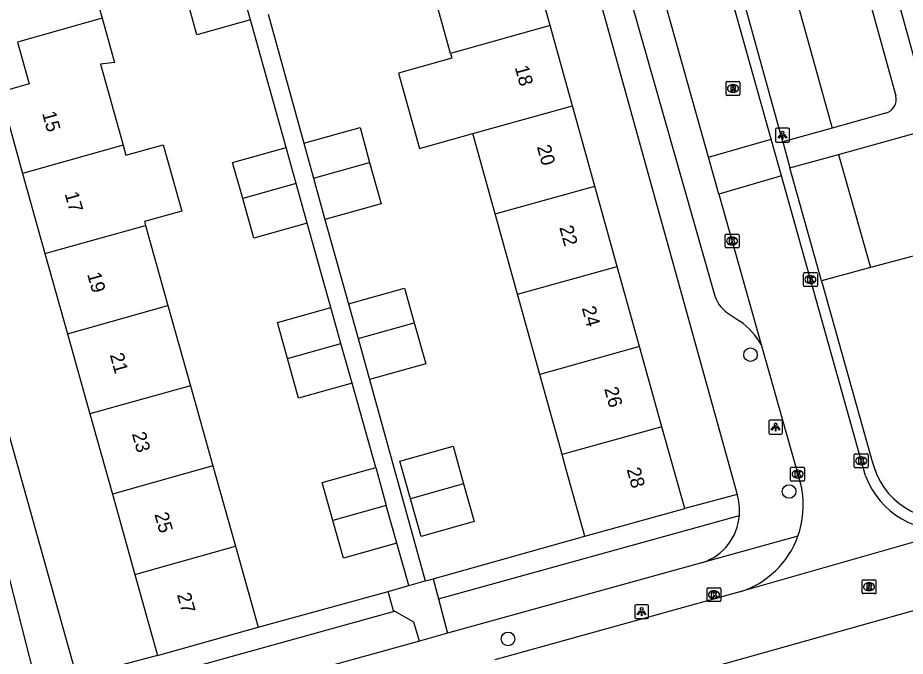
# Model space of a CAD drawing. Extents: x 159053 to 160041, y 380450 to 381422.
# Drawn here: x 159237.4 to 159301.4, y 380938.4 to 380984.4 of the extents above; entities that cross this region are included whole.
import ezdxf

# ---------------------------------------------------------------- set-up
doc = ezdxf.new("R2010")
doc.units = 0
for name, color, linetype in [('IMGEO_Boom', 7, 'Continuous'), ('IMGEO_Groenvoorziening', 7, 'Continuous'), ('IMGEO_Kolk', 7, 'Continuous'), ('IMGEO_Lichtpunt', 7, 'Continuous'), ('IMGEO_Pand', 7, 'Continuous'), ('IMGEO_Pand_nummerreeks', 7, 'Continuous'), ('IMGEO_Rijbaan_lokaal_open', 7, 'Continuous'), ('IMGEO_Rioolput', 7, 'Continuous'), ('IMGEO_Voetpad_halfverhard', 7, 'Continuous'), ('IMGEO_Voetpad_open', 7, 'Continuous')]:
    doc.layers.add(name, color=color, linetype=linetype)

msp = doc.modelspace()

# ---------------------------------------------------------------- linework, layer by layer
at = {"layer": 'IMGEO_Boom'}
for centre in [(159290.213, 380960.156), (159292.995, 380950.304), (159272.756, 380939.682)]:
    msp.add_circle(centre, 0.489, dxfattribs=at)
at = {"layer": 'IMGEO_Groenvoorziening'}
for points in [[(159291.218, 381004.807), (159292.969, 380998.465), (159290.211, 380997.678), (159296.09, 380976.486)], [(159296.56, 380974.584), (159298.858, 380966.431)], [(159308.436, 380968.993), (159298.858, 380966.431)], [(159298.858, 380966.431), (159295.334, 380965.488)], [(159289.244, 380950.092), (159285.477, 380949.072)], [(159267.741, 380942.562), (159289.412, 380948.582)], [(159267.352, 380944.011), (159278.291, 380947.073)], [(159254.754, 380940.525), (159264.121, 380943.101)], [(159242.353, 380935.51), (159264.567, 380941.681)], [(159247.51, 380938.496), (159241.698, 380936.943)]]:
    msp.add_lwpolyline(points, dxfattribs=at)
at = {"layer": 'IMGEO_Kolk'}
for p, q in [((159288.387, 380967.922), (159288.387, 380968.774)), ((159288.462, 380968.848), (159289.314, 380968.848)), ((159288.875, 380968.628), (159288.9, 380968.628)), ((159289.388, 380968.774), (159289.388, 380967.922)), ((159289.314, 380967.848), (159288.462, 380967.848)), ((159288.898, 380968.068), (159288.873, 380968.068)), ((159294.028, 380965.142), (159294.028, 380965.994)), ((159294.103, 380966.068), (159294.955, 380966.068)), ((159295.029, 380965.994), (159295.029, 380965.142)), ((159294.539, 380965.288), (159294.514, 380965.288)), ((159294.516, 380965.848), (159294.541, 380965.848)), ((159294.955, 380965.068), (159294.103, 380965.068)), ((159297.686, 380952.087), (159297.686, 380952.939)), ((159297.761, 380953.013), (159298.613, 380953.013)), ((159298.174, 380952.793), (159298.199, 380952.793)), ((159298.687, 380952.939), (159298.687, 380952.087)), ((159293.107, 380951.124), (159293.107, 380951.976)), ((159293.182, 380952.05), (159294.034, 380952.05)), ((159294.108, 380951.976), (159294.108, 380951.124)), ((159298.613, 380952.013), (159297.761, 380952.013)), ((159298.197, 380952.233), (159298.172, 380952.233)), ((159293.618, 380951.27), (159293.593, 380951.27)), ((159293.595, 380951.83), (159293.62, 380951.83)), ((159294.034, 380951.05), (159293.182, 380951.05)), ((159287.084, 380942.442), (159287.084, 380943.294)), ((159287.159, 380943.368), (159288.011, 380943.368)), ((159287.572, 380943.148), (159287.597, 380943.148)), ((159288.085, 380943.294), (159288.085, 380942.442)), ((159288.011, 380942.368), (159287.159, 380942.368)), ((159287.595, 380942.588), (159287.57, 380942.588))]:
    msp.add_line(p, q, dxfattribs=at)
for points in [[(159288.387, 380967.922), (159288.387, 380968.774)], [(159288.462, 380968.848), (159289.314, 380968.848)], [(159288.708, 380968.548), (159288.831, 380968.548), (159288.831, 380968.397), (159288.961, 380968.548), (159289.125, 380968.548), (159288.979, 380968.397), (159289.132, 380968.148), (159288.98, 380968.148), (159288.895, 380968.312), (159288.831, 380968.245), (159288.831, 380968.148), (159288.708, 380968.148), (159288.708, 380968.548)], [(159289.388, 380968.774), (159289.388, 380967.922)], [(159289.314, 380967.848), (159288.462, 380967.848)], [(159294.028, 380965.142), (159294.028, 380965.994)], [(159294.103, 380966.068), (159294.955, 380966.068)], [(159295.029, 380965.994), (159295.029, 380965.142)], [(159294.349, 380965.768), (159294.472, 380965.768), (159294.472, 380965.617), (159294.602, 380965.768), (159294.766, 380965.768), (159294.62, 380965.617), (159294.773, 380965.368), (159294.621, 380965.368), (159294.536, 380965.532), (159294.472, 380965.465), (159294.472, 380965.368), (159294.349, 380965.368), (159294.349, 380965.768)], [(159294.955, 380965.068), (159294.103, 380965.068)], [(159297.686, 380952.087), (159297.686, 380952.939)], [(159297.761, 380953.013), (159298.613, 380953.013)], [(159298.007, 380952.713), (159298.13, 380952.713), (159298.13, 380952.562), (159298.26, 380952.713), (159298.424, 380952.713), (159298.278, 380952.562), (159298.431, 380952.313), (159298.279, 380952.313), (159298.194, 380952.477), (159298.13, 380952.41), (159298.13, 380952.313), (159298.007, 380952.313), (159298.007, 380952.713)], [(159298.687, 380952.939), (159298.687, 380952.087)], [(159293.107, 380951.124), (159293.107, 380951.976)], [(159293.182, 380952.05), (159294.034, 380952.05)], [(159294.108, 380951.976), (159294.108, 380951.124)], [(159298.613, 380952.013), (159297.761, 380952.013)], [(159293.428, 380951.75), (159293.551, 380951.75), (159293.551, 380951.599), (159293.681, 380951.75), (159293.845, 380951.75), (159293.699, 380951.599), (159293.852, 380951.35), (159293.7, 380951.35), (159293.615, 380951.514), (159293.551, 380951.447), (159293.551, 380951.35), (159293.428, 380951.35), (159293.428, 380951.75)], [(159294.034, 380951.05), (159293.182, 380951.05)], [(159287.084, 380942.442), (159287.084, 380943.294)], [(159287.159, 380943.368), (159288.011, 380943.368)], [(159287.405, 380943.068), (159287.528, 380943.068), (159287.528, 380942.917), (159287.658, 380943.068), (159287.822, 380943.068), (159287.676, 380942.917), (159287.829, 380942.668), (159287.677, 380942.668), (159287.592, 380942.832), (159287.528, 380942.765), (159287.528, 380942.668), (159287.405, 380942.668), (159287.405, 380943.068)], [(159288.085, 380943.294), (159288.085, 380942.442)], [(159288.011, 380942.368), (159287.159, 380942.368)]]:
    msp.add_lwpolyline(points, dxfattribs=at)
for centre, start, end in [((159288.464, 380968.772), 91.55205, 178.44795), ((159288.464, 380968.772), 91.55205, 178.44795), ((159289.312, 380968.772), 1.55205, 88.44795), ((159289.312, 380968.772), 1.55205, 88.44795), ((159288.464, 380967.924), 181.55205, 268.44795), ((159288.464, 380967.924), 181.55205, 268.44795), ((159289.312, 380967.924), 271.55205, 358.44795), ((159289.312, 380967.924), 271.55205, 358.44795), ((159294.105, 380965.992), 91.55205, 178.44795), ((159294.105, 380965.992), 91.55205, 178.44795), ((159294.953, 380965.992), 1.55205, 88.44795), ((159294.953, 380965.992), 1.55205, 88.44795), ((159294.105, 380965.144), 181.55205, 268.44795), ((159294.105, 380965.144), 181.55205, 268.44795), ((159294.953, 380965.144), 271.55205, 358.44795), ((159294.953, 380965.144), 271.55205, 358.44795), ((159297.763, 380952.937), 91.55205, 178.44795), ((159297.763, 380952.937), 91.55205, 178.44795), ((159298.611, 380952.937), 1.55205, 88.44795), ((159298.611, 380952.937), 1.55205, 88.44795), ((159293.184, 380951.974), 91.55205, 178.44795), ((159293.184, 380951.974), 91.55205, 178.44795), ((159294.032, 380951.974), 1.55205, 88.44795), ((159294.032, 380951.974), 1.55205, 88.44795), ((159297.763, 380952.089), 181.55205, 268.44795), ((159297.763, 380952.089), 181.55205, 268.44795), ((159298.611, 380952.089), 271.55205, 358.44795), ((159298.611, 380952.089), 271.55205, 358.44795), ((159293.184, 380951.126), 181.55205, 268.44795), ((159293.184, 380951.126), 181.55205, 268.44795), ((159294.032, 380951.126), 271.55205, 358.44795), ((159294.032, 380951.126), 271.55205, 358.44795), ((159287.161, 380943.292), 91.55205, 178.44795), ((159287.161, 380943.292), 91.55205, 178.44795), ((159288.009, 380943.292), 1.55205, 88.44795), ((159288.009, 380943.292), 1.55205, 88.44795), ((159287.161, 380942.444), 181.55205, 268.44795), ((159287.161, 380942.444), 181.55205, 268.44795), ((159288.009, 380942.444), 271.55205, 358.44795), ((159288.009, 380942.444), 271.55205, 358.44795)]:
    msp.add_arc(centre, 0.0765, start, end, dxfattribs=at)
for centre, major_axis, ratio, start_param, end_param in [((159288.874, 380968.348), (-0.387, 0.002), 0.722429, 4.712389, 7.853982), ((159288.899, 380968.348), (-0.39, 0.002), 0.717154, 1.570796, 4.712389), ((159294.515, 380965.568), (-0.387, 0.002), 0.722429, 4.712389, 7.853982), ((159294.54, 380965.568), (-0.39, 0.002), 0.717154, 1.570796, 4.712389), ((159298.173, 380952.513), (-0.387, 0.002), 0.722429, 4.712389, 7.853982), ((159298.198, 380952.513), (-0.39, 0.002), 0.717154, 1.570796, 4.712389), ((159293.594, 380951.55), (-0.387, 0.002), 0.722429, 4.712389, 7.853982), ((159293.619, 380951.55), (-0.39, 0.002), 0.717154, 1.570796, 4.712389), ((159287.571, 380942.868), (-0.387, 0.002), 0.722429, 4.712389, 7.853982), ((159287.596, 380942.868), (-0.39, 0.002), 0.717154, 1.570796, 4.712389)]:
    msp.add_ellipse(centre, major_axis=major_axis, ratio=ratio, start_param=start_param, end_param=end_param, dxfattribs=at)
at = {"layer": 'IMGEO_Lichtpunt'}
for p, q in [((159292.02, 380976.373), (159292.02, 380975.566)), ((159292.02, 380976.373), (159292.02, 380975.566)), ((159292.922, 380976.468), (159292.114, 380976.468)), ((159292.922, 380976.468), (159292.114, 380976.468)), ((159293.016, 380975.566), (159293.016, 380976.373)), ((159293.016, 380975.566), (159293.016, 380976.373)), ((159292.114, 380975.472), (159292.922, 380975.472)), ((159292.114, 380975.472), (159292.922, 380975.472)), ((159291.528, 380955.344), (159291.528, 380954.537)), ((159291.528, 380955.344), (159291.528, 380954.537)), ((159292.43, 380955.439), (159291.622, 380955.439)), ((159292.43, 380955.439), (159291.622, 380955.439)), ((159292.524, 380954.537), (159292.524, 380955.344)), ((159292.524, 380954.537), (159292.524, 380955.344)), ((159291.622, 380954.443), (159292.43, 380954.443)), ((159291.622, 380954.443), (159292.43, 380954.443)), ((159281.877, 380942.045), (159281.877, 380941.238)), ((159281.877, 380942.045), (159281.877, 380941.238)), ((159282.779, 380942.14), (159281.971, 380942.14)), ((159282.779, 380942.14), (159281.971, 380942.14)), ((159282.873, 380941.238), (159282.873, 380942.045)), ((159282.873, 380941.238), (159282.873, 380942.045)), ((159281.971, 380941.144), (159282.779, 380941.144)), ((159281.971, 380941.144), (159282.779, 380941.144))]:
    msp.add_line(p, q, dxfattribs=at)
for points in [[(159292.394, 380976.037), (159292.433, 380976.009), (159292.245, 380975.747), (159292.207, 380975.774), (159292.394, 380976.037)], [(159292.496, 380975.989), (159292.543, 380975.989), (159292.543, 380975.667), (159292.496, 380975.667), (159292.496, 380975.989)], [(159292.606, 380976.009), (159292.644, 380976.036), (159292.831, 380975.774), (159292.792, 380975.746), (159292.606, 380976.009)], [(159291.902, 380955.008), (159291.941, 380954.98), (159291.753, 380954.718), (159291.715, 380954.745), (159291.902, 380955.008)], [(159292.004, 380954.96), (159292.051, 380954.96), (159292.051, 380954.638), (159292.004, 380954.638), (159292.004, 380954.96)], [(159292.114, 380954.98), (159292.152, 380955.007), (159292.339, 380954.745), (159292.3, 380954.717), (159292.114, 380954.98)], [(159282.251, 380941.709), (159282.29, 380941.681), (159282.102, 380941.419), (159282.064, 380941.446), (159282.251, 380941.709)], [(159282.353, 380941.661), (159282.4, 380941.661), (159282.4, 380941.339), (159282.353, 380941.339), (159282.353, 380941.661)], [(159282.463, 380941.681), (159282.501, 380941.708), (159282.688, 380941.446), (159282.649, 380941.418), (159282.463, 380941.681)]]:
    msp.add_lwpolyline(points, dxfattribs=at)
for centre in [(159292.519, 380976.171), (159292.027, 380955.142), (159282.376, 380941.843)]:
    msp.add_circle(centre, 0.0994, dxfattribs=at)
for centre, start, end in [((159292.114, 380976.373), 90, 180), ((159292.114, 380976.373), 90, 180), ((159292.922, 380976.373), 0, 90), ((159292.922, 380976.373), 0, 90), ((159292.114, 380975.566), 180, 270), ((159292.114, 380975.566), 180, 270), ((159292.922, 380975.566), 270, 0), ((159292.922, 380975.566), 270, 360), ((159291.622, 380955.344), 90, 180), ((159291.622, 380955.344), 90, 180), ((159292.43, 380955.344), 0, 90), ((159292.43, 380955.344), 0, 90), ((159291.622, 380954.537), 180, 270), ((159291.622, 380954.537), 180, 270), ((159292.43, 380954.537), 270, 0), ((159292.43, 380954.537), 270, 360), ((159281.971, 380942.045), 90, 180), ((159281.971, 380942.045), 90, 180), ((159282.779, 380942.045), 0, 90), ((159282.779, 380942.045), 0, 90), ((159281.971, 380941.238), 180, 270), ((159281.971, 380941.238), 180, 270), ((159282.779, 380941.238), 270, 0), ((159282.779, 380941.238), 270, 360)]:
    msp.add_arc(centre, 0.0946, start, end, dxfattribs=at)
at = {"layer": 'IMGEO_Pand'}
for points in [[(159240.059, 380992.998), (159241.716, 380987.082), (159242.057, 380987.178), (159241.964, 380987.512), (159242.612, 380987.675), (159243.532, 380984.388)], [(159275.799, 380983.86), (159274.162, 380989.745), (159272.231, 380989.208), (159271.406, 380992.175)], [(159268.614, 380981.861), (159266.972, 380987.762), (159266.594, 380987.656), (159266.691, 380987.308), (159265.976, 380987.109), (159265.058, 380990.409)], [(159254.202, 380984.271), (159253.386, 380987.183)], [(159254.202, 380984.271), (159250.351, 380983.192), (159249.537, 380986.098)], [(159243.532, 380984.388), (159237.431, 380982.682)], [(159243.532, 380984.388), (159244.422, 380981.211), (159243.392, 380981.09), (159245.028, 380975.25)], [(159275.799, 380983.86), (159268.614, 380981.861)], [(159277.407, 380978.079), (159275.799, 380983.86)], [(159237.431, 380982.682), (159238.277, 380979.658), (159236.148, 380979.061), (159237.784, 380973.221)], [(159268.614, 380981.861), (159268.711, 380981.511), (159264.867, 380980.442), (159266.378, 380975.011), (159270.222, 380976.08)], [(159270.222, 380976.08), (159277.407, 380978.079)], [(159279.015, 380972.299), (159277.407, 380978.079)], [(159258.05, 380975.387), (159262.096, 380976.513), (159262.786, 380974.011)], [(159271.83, 380970.3), (159270.222, 380976.08)], [(159245.028, 380975.25), (159237.784, 380973.221)], [(159245.028, 380975.25), (159245.231, 380974.525), (159247.922, 380975.278), (159249.258, 380970.508), (159246.567, 380969.755), (159246.646, 380969.472)], [(159253.643, 380971.41), (159252.919, 380973.994), (159256.769, 380975.073)], [(159257.493, 380972.489), (159256.769, 380975.073)], [(159258.05, 380975.387), (159258.74, 380972.885)], [(159258.74, 380972.885), (159262.786, 380974.011)], [(159262.786, 380974.011), (159263.611, 380971.018), (159259.562, 380969.902)], [(159237.784, 380973.221), (159239.402, 380967.443)], [(159257.493, 380972.489), (159253.643, 380971.41)], [(159258.296, 380969.625), (159257.493, 380972.489)], [(159258.74, 380972.885), (159259.562, 380969.902)], [(159271.83, 380970.3), (159279.015, 380972.299)], [(159280.624, 380966.518), (159279.015, 380972.299)], [(159258.296, 380969.625), (159254.445, 380968.546), (159253.643, 380971.41)], [(159273.438, 380964.52), (159271.83, 380970.3)], [(159239.402, 380967.443), (159246.646, 380969.472)], [(159246.646, 380969.472), (159248.264, 380963.695)], [(159239.402, 380967.443), (159241.02, 380961.666)], [(159273.438, 380964.52), (159280.624, 380966.518)], [(159282.232, 380960.737), (159280.624, 380966.518)], [(159261.267, 380963.827), (159265.305, 380964.951), (159266, 380962.452)], [(159275.046, 380958.739), (159273.438, 380964.52)], [(159241.02, 380961.666), (159248.264, 380963.695)], [(159248.264, 380963.695), (159249.882, 380957.917)], [(159256.871, 380959.884), (159256.147, 380962.468), (159259.997, 380963.547)], [(159260.721, 380960.963), (159259.997, 380963.547)], [(159261.267, 380963.827), (159261.962, 380961.329)], [(159261.962, 380961.329), (159266, 380962.452)], [(159266, 380962.452), (159266.823, 380959.496), (159262.784, 380958.373)], [(159241.02, 380961.666), (159242.639, 380955.888)], [(159256.871, 380959.884), (159260.721, 380960.963)], [(159261.524, 380958.099), (159260.721, 380960.963)], [(159261.962, 380961.329), (159262.784, 380958.373)], [(159282.232, 380960.737), (159275.046, 380958.739)], [(159283.84, 380954.957), (159282.232, 380960.737)], [(159261.524, 380958.099), (159257.673, 380957.02), (159256.871, 380959.884)], [(159276.654, 380952.959), (159275.046, 380958.739)], [(159249.882, 380957.917), (159242.639, 380955.888)], [(159249.882, 380957.917), (159251.501, 380952.139)], [(159242.639, 380955.888), (159244.257, 380950.11)], [(159283.84, 380954.957), (159276.654, 380952.959)], [(159285.477, 380949.072), (159283.84, 380954.957)], [(159265.728, 380949.778), (159264.97, 380952.486), (159268.794, 380953.557), (159269.553, 380950.849)], [(159278.291, 380947.073), (159276.951, 380951.891), (159276.654, 380952.959)], [(159251.501, 380952.139), (159244.257, 380950.11)], [(159251.501, 380952.139), (159253.119, 380946.362)], [(159260.137, 380948.22), (159259.374, 380950.944), (159263.224, 380952.023)], [(159263.224, 380952.023), (159263.988, 380949.299)], [(159269.553, 380950.849), (159270.311, 380948.141), (159266.487, 380947.07), (159265.728, 380949.778)], [(159269.553, 380950.849), (159265.728, 380949.778)], [(159244.257, 380950.11), (159245.875, 380944.333)], [(159263.988, 380949.299), (159260.137, 380948.22)], [(159264.751, 380946.575), (159263.988, 380949.299)], [(159278.291, 380947.073), (159285.477, 380949.072)], [(159264.751, 380946.575), (159260.9, 380945.496), (159260.137, 380948.22)], [(159245.875, 380944.333), (159253.119, 380946.362)], [(159253.119, 380946.362), (159253.405, 380945.34), (159254.754, 380940.525)], [(159245.875, 380944.333), (159247.51, 380938.496)], [(159247.51, 380938.496), (159254.754, 380940.525)]]:
    msp.add_lwpolyline(points, dxfattribs=at)
at = {"layer": 'IMGEO_Rijbaan_lokaal_open'}
for points in [[(159291.694, 380975.682), (159288.716, 380986.309), (159281.874, 381011.139)], [(159287.197, 380974.398), (159283.575, 380987.338), (159283.051, 380989.219)], [(159287.197, 380974.398), (159291.694, 380975.682)], [(159292.436, 380973.036), (159291.694, 380975.682)], [(159287.946, 380971.724), (159287.197, 380974.398)], [(159292.436, 380973.036), (159287.946, 380971.724)], [(159298.493, 380951.423), (159292.436, 380973.036)], [(159287.946, 380971.724), (159290.55, 380962.421), (159290.983, 380960.885)], [(159290.983, 380960.885), (159293.733, 380951.114), (159293.914, 380950.469)], [(159238.874, 380936.156), (159234.335, 380953.821), (159233.764, 380955.863)], [(159305.085, 380947.551), (159289.451, 380943.067)], [(159309.441, 380943.822), (159291.177, 380938.669), (159273.09, 380933.625)], [(159289.451, 380943.067), (159271.799, 380938.174)]]:
    msp.add_lwpolyline(points, dxfattribs=at)
for centre, radius, start, end in [((159304.202, 380953.596), 6.109, 200.83487, 278.30699), ((159287.468, 380949.308), 6.55, 340.23791, 10.21234), ((159287.467, 380949.311), 6.552, 287.62449, 340.21155)]:
    msp.add_arc(centre, radius, start, end, dxfattribs=at)
at = {"layer": 'IMGEO_Rioolput'}
for p, q in [((159288.451, 380978.908), (159288.451, 380979.76)), ((159288.526, 380979.834), (159289.378, 380979.834)), ((159288.939, 380979.614), (159288.964, 380979.614)), ((159289.452, 380979.76), (159289.452, 380978.908)), ((159289.378, 380978.834), (159288.526, 380978.834)), ((159288.962, 380979.054), (159288.937, 380979.054)), ((159298.252, 380943.017), (159298.252, 380943.869)), ((159298.327, 380943.943), (159299.179, 380943.943)), ((159298.74, 380943.723), (159298.765, 380943.723)), ((159299.253, 380943.869), (159299.253, 380943.017)), ((159299.179, 380942.943), (159298.327, 380942.943)), ((159298.763, 380943.163), (159298.738, 380943.163))]:
    msp.add_line(p, q, dxfattribs=at)
for points in [[(159288.451, 380978.908), (159288.451, 380979.76)], [(159288.526, 380979.834), (159289.378, 380979.834)], [(159289.04, 380979.532), (159288.788, 380979.534), (159288.788, 380979.134)], [(159288.966, 380979.453), (159288.912, 380979.453), (159288.912, 380979.372)], [(159288.912, 380979.372), (159288.964, 380979.372)], [(159289.452, 380979.76), (159289.452, 380978.908)], [(159289.378, 380978.834), (159288.526, 380978.834)], [(159288.788, 380979.134), (159288.912, 380979.134), (159288.912, 380979.296), (159288.923, 380979.296)], [(159288.97, 380979.267), (159289.041, 380979.134), (159289.181, 380979.134), (159289.116, 380979.26)], [(159298.252, 380943.017), (159298.252, 380943.869)], [(159298.327, 380943.943), (159299.179, 380943.943)], [(159298.841, 380943.641), (159298.589, 380943.643), (159298.589, 380943.243)], [(159298.767, 380943.562), (159298.713, 380943.562), (159298.713, 380943.481)], [(159299.253, 380943.869), (159299.253, 380943.017)], [(159299.179, 380942.943), (159298.327, 380942.943)], [(159298.589, 380943.243), (159298.713, 380943.243), (159298.713, 380943.405), (159298.724, 380943.405)], [(159298.713, 380943.481), (159298.765, 380943.481)], [(159298.771, 380943.376), (159298.842, 380943.243), (159298.982, 380943.243), (159298.917, 380943.369)]]:
    msp.add_lwpolyline(points, dxfattribs=at)
for centre, radius, start, end in [((159288.528, 380979.758), 0.0765, 91.55205, 178.44795), ((159288.528, 380979.758), 0.0765, 91.55205, 178.44795), ((159288.948, 380979.561), 0.19, 274.7715, 282.96867), ((159288.972, 380979.357), 0.0964, 77.00612, 93.18647), ((159288.986, 380979.414), 0.0378, 276.66336, 79.67722), ((159289.039, 380979.422), 0.109, 350.36119, 89.41601), ((159289.037, 380979.422), 0.112, 277.58423, 350.98172), ((159289.376, 380979.758), 0.0765, 1.55205, 88.44795), ((159289.376, 380979.758), 0.0765, 1.55205, 88.44795), ((159288.528, 380978.91), 0.0765, 181.55205, 268.44795), ((159288.528, 380978.91), 0.0765, 181.55205, 268.44795), ((159288.922, 380979.243), 0.0533, 26.02933, 88.69889), ((159289.021, 380979.207), 0.108, 29.51342, 73.79051), ((159289.376, 380978.91), 0.0765, 271.55205, 358.44795), ((159289.376, 380978.91), 0.0765, 271.55205, 358.44795), ((159298.329, 380943.867), 0.0765, 91.55205, 178.44795), ((159298.329, 380943.867), 0.0765, 91.55205, 178.44795), ((159298.773, 380943.466), 0.0964, 77.00612, 93.18647), ((159298.787, 380943.523), 0.0378, 276.66336, 79.67722), ((159298.84, 380943.531), 0.109, 350.36119, 89.41601), ((159299.177, 380943.867), 0.0765, 1.55205, 88.44795), ((159299.177, 380943.867), 0.0765, 1.55205, 88.44795), ((159298.329, 380943.019), 0.0765, 181.55205, 268.44795), ((159298.329, 380943.019), 0.0765, 181.55205, 268.44795), ((159298.723, 380943.352), 0.0533, 26.02933, 88.69889), ((159298.749, 380943.67), 0.19, 274.7715, 282.96867), ((159298.838, 380943.531), 0.112, 277.58423, 350.98172), ((159298.822, 380943.316), 0.108, 29.51342, 73.79051), ((159299.177, 380943.019), 0.0765, 271.55205, 358.44795), ((159299.177, 380943.019), 0.0765, 271.55205, 358.44795)]:
    msp.add_arc(centre, radius, start, end, dxfattribs=at)
for centre, major_axis, ratio, start_param, end_param in [((159288.938, 380979.334), (-0.387, 0.002), 0.722429, 4.712389, 7.853982), ((159288.963, 380979.334), (-0.39, 0.002), 0.717154, 1.570796, 4.712389), ((159298.739, 380943.443), (-0.387, 0.002), 0.722429, 4.712389, 7.853982), ((159298.764, 380943.443), (-0.39, 0.002), 0.717154, 1.570796, 4.712389)]:
    msp.add_ellipse(centre, major_axis=major_axis, ratio=ratio, start_param=start_param, end_param=end_param, dxfattribs=at)
at = {"layer": 'IMGEO_Voetpad_halfverhard'}
for points in [[(159293.692, 381004.092), (159300.679, 380978.809)], [(159302.411, 380980.049), (159295.836, 381003.844)], [(159299.932, 380977.551), (159296.09, 380976.486)], [(159296.09, 380976.486), (159292.532, 380975.5)], [(159296.56, 380974.584), (159302.684, 380976.292)], [(159293.056, 380973.607), (159296.56, 380974.584)]]:
    msp.add_lwpolyline(points, dxfattribs=at)
msp.add_arc((159299.662, 380978.562), 1.047, 284.9491, 13.64725, dxfattribs=at)
at = {"layer": 'IMGEO_Voetpad_open'}
for points in [[(159265.037, 381037.32), (159275.394, 381000), (159289.244, 380950.092)], [(159241.698, 380936.943), (159224.043, 381000), (159217.284, 381024.142)], [(159292.532, 380975.5), (159284.91, 381003.085)], [(159281.709, 380985.241), (159287.631, 380964.481)], [(159255.49, 380984.696), (159258.05, 380975.387)], [(159256.769, 380975.073), (159254.202, 380984.271)], [(159292.532, 380975.5), (159293.056, 380973.607)], [(159295.334, 380965.488), (159293.056, 380973.607)], [(159259.562, 380969.902), (159261.267, 380963.827)], [(159259.997, 380963.547), (159258.296, 380969.625)], [(159295.334, 380965.488), (159298.988, 380952.473)], [(159288.522, 380963.194), (159289.445, 380962.57)], [(159262.784, 380958.373), (159266.796, 380943.855)], [(159263.224, 380952.023), (159261.524, 380958.099)], [(159293.632, 380947.093), (159286.78, 380945.193)], [(159265.611, 380943.521), (159264.751, 380946.575)], [(159286.78, 380945.193), (159268.403, 380940.097)], [(159265.611, 380943.521), (159266.796, 380943.855)], [(159266.796, 380943.855), (159267.352, 380944.011)], [(159267.352, 380944.011), (159267.741, 380942.562)], [(159264.121, 380943.101), (159265.611, 380943.521)], [(159264.567, 380941.681), (159264.514, 380941.711), (159264.121, 380943.101)], [(159267.741, 380942.562), (159268.403, 380940.097)], [(159266.365, 380939.531), (159265.98, 380940.881), (159264.567, 380941.681)], [(159268.403, 380940.097), (159266.365, 380939.531)], [(159266.365, 380939.531), (159246.921, 380934.139)]]:
    msp.add_lwpolyline(points, dxfattribs=at)
for centre, radius, start, end in [((159289.797, 380965.028), 2.234, 194.18408, 235.20623), ((159286.457, 380958.298), 5.213, 29.74926, 55.02788), ((159304.304, 380953.725), 5.461, 193.25133, 280.01252), ((159285.512, 380948.912), 3.914, 355.15664, 17.5404), ((159285.576, 380948.845), 3.845, 288.24784, 356.08417)]:
    msp.add_arc(centre, radius, start, end, dxfattribs=at)

# ---------------------------------------------------------------- texts
at = {"layer": 'IMGEO_Pand_nummerreeks'}
for s, rotation, p in [('18', 285.54413, (159273.23, 380980.855)), ('15', 285.64722, (159239.188, 380977.551)), ('20', 285.54627, (159274.822, 380975.133)), ('17', 285.64727, (159240.811, 380971.757)), ('22', 285.54627, (159276.437, 380969.328)), ('19', 285.64722, (159242.434, 380965.961)), ('24', 285.54627, (159278.054, 380963.515)), ('21', 285.64722, (159244.064, 380960.145)), ('26', 285.54627, (159279.67, 380957.704)), ('23', 285.64722, (159245.656, 380954.459)), ('28', 285.54627, (159281.288, 380951.891)), ('25', 285.64722, (159247.279, 380948.664)), ('27', 285.64722, (159248.902, 380942.869))]:
    msp.add_text(s, height=1, rotation=rotation, dxfattribs=at).set_placement(p)

doc.saveas('drawing.dxf')
